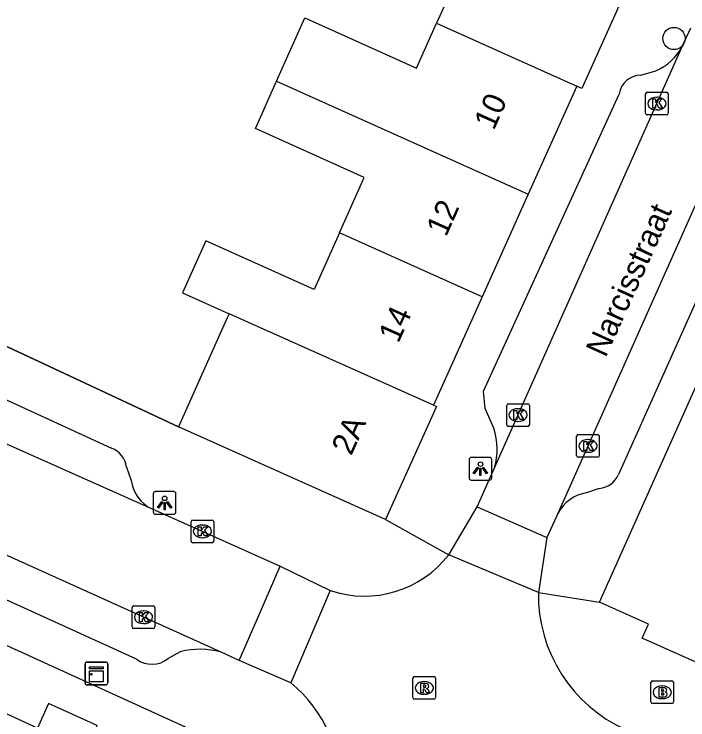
# Model space of a CAD drawing. Extents: x 161845 to 162341, y 381620 to 382158.
# Drawn here: x 162150.69 to 162180.36, y 381756.3 to 381787.37 of the extents above; entities that cross this region are included whole.
import ezdxf

# ---------------------------------------------------------------- set-up
doc = ezdxf.new("R2010")
doc.units = 0
for name, color, linetype in [('IMGEO_Boom', 7, 'Continuous'), ('IMGEO_Brandkraan', 7, 'Continuous'), ('IMGEO_Kast', 7, 'Continuous'), ('IMGEO_Kolk', 7, 'Continuous'), ('IMGEO_Lichtpunt', 7, 'Continuous'), ('IMGEO_Muur', 7, 'Continuous'), ('IMGEO_Openbare_ruimte_label', 7, 'Continuous'), ('IMGEO_Pand', 7, 'Continuous'), ('IMGEO_Pand_nummerreeks', 7, 'Continuous'), ('IMGEO_Rijbaan_lokaal_open', 7, 'Continuous'), ('IMGEO_Rioolput', 7, 'Continuous'), ('IMGEO_Voetpad_open', 7, 'Continuous')]:
    doc.layers.add(name, color=color, linetype=linetype)

msp = doc.modelspace()

# ---------------------------------------------------------------- linework, layer by layer
at = {"layer": 'IMGEO_Boom'}
msp.add_circle((162179.746, 381786.3), 0.489, dxfattribs=at)
at = {"layer": 'IMGEO_Brandkraan'}
for p, q in [((162178.728, 381757.091), (162178.728, 381757.943)), ((162178.803, 381758.017), (162179.655, 381758.017)), ((162179.216, 381757.797), (162179.241, 381757.797)), ((162179.729, 381757.943), (162179.729, 381757.091)), ((162179.239, 381757.237), (162179.214, 381757.237)), ((162179.655, 381757.017), (162178.803, 381757.017))]:
    msp.add_line(p, q, dxfattribs=at)
for points in [[(162178.728, 381757.091), (162178.728, 381757.943)], [(162178.803, 381758.017), (162179.655, 381758.017)], [(162179.729, 381757.943), (162179.729, 381757.091)], [(162179.076, 381757.717), (162179.076, 381757.317), (162179.289, 381757.317)], [(162179.307, 381757.717), (162179.076, 381757.717)], [(162179.255, 381757.636), (162179.201, 381757.636), (162179.201, 381757.56)], [(162179.201, 381757.56), (162179.254, 381757.56)], [(162179.263, 381757.484), (162179.201, 381757.484), (162179.201, 381757.403)], [(162179.201, 381757.403), (162179.263, 381757.403)], [(162179.655, 381757.017), (162178.803, 381757.017)]]:
    msp.add_lwpolyline(points, dxfattribs=at)
for centre, radius, start, end in [((162178.805, 381757.941), 0.0765, 91.552, 178.448), ((162178.805, 381757.941), 0.0765, 91.552, 178.448), ((162179.653, 381757.941), 0.0765, 1.552, 88.448), ((162179.653, 381757.941), 0.0765, 1.552, 88.448), ((162179.256, 381757.598), 0.0379, 267.8285, 90.9355), ((162179.264, 381757.443), 0.0404, 269.8759, 90.5077), ((162179.311, 381757.572), 0.145, 59.4692, 91.5367), ((162179.336, 381757.619), 0.0922, 285.5137, 58.1501), ((162179.341, 381757.427), 0.105, 301.3115, 78.989), ((162179.295, 381757.568), 0.251, 268.6676, 293.5347), ((162178.805, 381757.093), 0.0765, 181.552, 268.448), ((162178.805, 381757.093), 0.0765, 181.552, 268.448), ((162179.653, 381757.093), 0.0765, 271.552, 358.448), ((162179.653, 381757.093), 0.0765, 271.552, 358.448)]:
    msp.add_arc(centre, radius, start, end, dxfattribs=at)
for centre, major_axis, ratio, start_param, end_param in [((162179.215, 381757.517), (-0.387, 0.002), 0.722429, 4.712389, 7.853982), ((162179.24, 381757.517), (-0.39, 0.002), 0.717154, 1.570796, 4.712389)]:
    msp.add_ellipse(centre, major_axis=major_axis, ratio=ratio, start_param=start_param, end_param=end_param, dxfattribs=at)
at = {"layer": 'IMGEO_Kast'}
for p, q in [((162153.808, 381757.922), (162153.808, 381758.763)), ((162153.808, 381758.763), (162153.808, 381757.922)), ((162153.883, 381758.847), (162154.724, 381758.847)), ((162154.724, 381758.847), (162153.883, 381758.847)), ((162154.808, 381758.772), (162154.808, 381757.931)), ((162154.808, 381757.931), (162154.808, 381758.772)), ((162154.733, 381757.847), (162153.892, 381757.847)), ((162153.892, 381757.847), (162154.733, 381757.847))]:
    msp.add_line(p, q, dxfattribs=at)
for points in [[(162154.003, 381758.637), (162154.603, 381758.637), (162154.603, 381758.552), (162154.003, 381758.552), (162154.003, 381758.637)], [(162154.003, 381758.462), (162154.603, 381758.462), (162154.603, 381757.973), (162154.003, 381757.973), (162154.003, 381758.462)]]:
    msp.add_lwpolyline(points, dxfattribs=at)
msp.add_circle((162154.087, 381758.311), 0.0377, dxfattribs=at)
for centre, start, end in [((162153.886, 381758.769), 92.4484, 184.2845), ((162153.886, 381758.769), 92.4484, 184.2845), ((162154.73, 381758.769), 2.4484, 94.2845), ((162154.73, 381758.769), 2.4484, 94.2845), ((162153.886, 381757.925), 182.4484, 274.2845), ((162153.886, 381757.925), 182.4484, 274.2845), ((162154.73, 381757.925), 272.4484, 4.2845), ((162154.73, 381757.925), 272.4484, 4.2845)]:
    msp.add_arc(centre, 0.0779, start, end, dxfattribs=at)
at = {"layer": 'IMGEO_Kolk'}
for p, q in [((162178.569, 381783.937), (162179.421, 381783.937)), ((162178.494, 381783.011), (162178.494, 381783.863)), ((162178.982, 381783.717), (162179.007, 381783.717)), ((162179.495, 381783.863), (162179.495, 381783.011)), ((162179.005, 381783.157), (162178.98, 381783.157)), ((162179.421, 381782.937), (162178.569, 381782.937)), ((162172.455, 381770.222), (162173.307, 381770.222)), ((162172.38, 381769.296), (162172.38, 381770.148)), ((162172.868, 381770.002), (162172.893, 381770.002)), ((162173.381, 381770.148), (162173.381, 381769.296)), ((162172.891, 381769.442), (162172.866, 381769.442)), ((162173.307, 381769.222), (162172.455, 381769.222)), ((162175.458, 381767.939), (162175.458, 381768.791)), ((162175.533, 381768.865), (162176.385, 381768.865)), ((162176.459, 381768.791), (162176.459, 381767.939)), ((162175.946, 381768.645), (162175.971, 381768.645)), ((162175.969, 381768.085), (162175.944, 381768.085)), ((162176.385, 381767.865), (162175.533, 381767.865)), ((162158.478, 381764.174), (162158.478, 381765.026)), ((162158.553, 381765.1), (162159.405, 381765.1)), ((162159.479, 381765.026), (162159.479, 381764.174)), ((162158.966, 381764.88), (162158.991, 381764.88)), ((162158.989, 381764.32), (162158.964, 381764.32)), ((162159.405, 381764.1), (162158.553, 381764.1)), ((162155.884, 381760.397), (162155.884, 381761.249)), ((162155.959, 381761.323), (162156.811, 381761.323)), ((162156.885, 381761.249), (162156.885, 381760.397)), ((162156.372, 381761.103), (162156.397, 381761.103)), ((162156.811, 381760.323), (162155.959, 381760.323)), ((162156.395, 381760.543), (162156.37, 381760.543))]:
    msp.add_line(p, q, dxfattribs=at)
for points in [[(162178.569, 381783.937), (162179.421, 381783.937)], [(162178.494, 381783.011), (162178.494, 381783.863)], [(162178.815, 381783.637), (162178.938, 381783.637), (162178.938, 381783.486), (162179.068, 381783.637), (162179.232, 381783.637), (162179.086, 381783.486), (162179.239, 381783.237), (162179.087, 381783.237), (162179.002, 381783.401), (162178.938, 381783.334), (162178.938, 381783.237), (162178.815, 381783.237), (162178.815, 381783.637)], [(162179.495, 381783.863), (162179.495, 381783.011)], [(162179.421, 381782.937), (162178.569, 381782.937)], [(162172.455, 381770.222), (162173.307, 381770.222)], [(162172.38, 381769.296), (162172.38, 381770.148)], [(162172.701, 381769.922), (162172.824, 381769.922), (162172.824, 381769.771), (162172.954, 381769.922), (162173.118, 381769.922), (162172.972, 381769.771), (162173.125, 381769.522), (162172.973, 381769.522), (162172.888, 381769.686), (162172.824, 381769.619), (162172.824, 381769.522), (162172.701, 381769.522), (162172.701, 381769.922)], [(162173.381, 381770.148), (162173.381, 381769.296)], [(162173.307, 381769.222), (162172.455, 381769.222)], [(162175.458, 381767.939), (162175.458, 381768.791)], [(162175.533, 381768.865), (162176.385, 381768.865)], [(162176.459, 381768.791), (162176.459, 381767.939)], [(162175.779, 381768.565), (162175.902, 381768.565), (162175.902, 381768.414), (162176.032, 381768.565), (162176.196, 381768.565), (162176.05, 381768.414), (162176.203, 381768.165), (162176.051, 381768.165), (162175.966, 381768.329), (162175.902, 381768.262), (162175.902, 381768.165), (162175.779, 381768.165), (162175.779, 381768.565)], [(162176.385, 381767.865), (162175.533, 381767.865)], [(162158.478, 381764.174), (162158.478, 381765.026)], [(162158.553, 381765.1), (162159.405, 381765.1)], [(162159.479, 381765.026), (162159.479, 381764.174)], [(162158.799, 381764.8), (162158.922, 381764.8), (162158.922, 381764.649), (162159.052, 381764.8), (162159.216, 381764.8), (162159.07, 381764.649), (162159.223, 381764.4), (162159.071, 381764.4), (162158.986, 381764.564), (162158.922, 381764.497), (162158.922, 381764.4), (162158.799, 381764.4), (162158.799, 381764.8)], [(162159.405, 381764.1), (162158.553, 381764.1)], [(162155.884, 381760.397), (162155.884, 381761.249)], [(162155.959, 381761.323), (162156.811, 381761.323)], [(162156.885, 381761.249), (162156.885, 381760.397)], [(162156.205, 381761.023), (162156.328, 381761.023), (162156.328, 381760.872), (162156.458, 381761.023), (162156.622, 381761.023), (162156.476, 381760.872), (162156.629, 381760.623), (162156.477, 381760.623), (162156.392, 381760.787), (162156.328, 381760.72), (162156.328, 381760.623), (162156.205, 381760.623), (162156.205, 381761.023)], [(162156.811, 381760.323), (162155.959, 381760.323)]]:
    msp.add_lwpolyline(points, dxfattribs=at)
for centre, start, end in [((162178.571, 381783.861), 91.552, 178.448), ((162178.571, 381783.861), 91.552, 178.448), ((162179.419, 381783.861), 1.552, 88.448), ((162179.419, 381783.861), 1.552, 88.448), ((162178.571, 381783.013), 181.552, 268.448), ((162178.571, 381783.013), 181.552, 268.448), ((162179.419, 381783.013), 271.552, 358.448), ((162179.419, 381783.013), 271.552, 358.448), ((162172.457, 381770.146), 91.552, 178.448), ((162172.457, 381770.146), 91.552, 178.448), ((162173.305, 381770.146), 1.552, 88.448), ((162173.305, 381770.146), 1.552, 88.448), ((162172.457, 381769.298), 181.552, 268.448), ((162172.457, 381769.298), 181.552, 268.448), ((162173.305, 381769.298), 271.552, 358.448), ((162173.305, 381769.298), 271.552, 358.448), ((162175.535, 381768.789), 91.552, 178.448), ((162175.535, 381768.789), 91.552, 178.448), ((162176.383, 381768.789), 1.552, 88.448), ((162176.383, 381768.789), 1.552, 88.448), ((162175.535, 381767.941), 181.552, 268.448), ((162175.535, 381767.941), 181.552, 268.448), ((162176.383, 381767.941), 271.552, 358.448), ((162176.383, 381767.941), 271.552, 358.448), ((162158.555, 381765.024), 91.552, 178.448), ((162158.555, 381765.024), 91.552, 178.448), ((162159.403, 381765.024), 1.552, 88.448), ((162159.403, 381765.024), 1.552, 88.448), ((162158.555, 381764.176), 181.552, 268.448), ((162158.555, 381764.176), 181.552, 268.448), ((162159.403, 381764.176), 271.552, 358.448), ((162159.403, 381764.176), 271.552, 358.448), ((162155.961, 381761.247), 91.552, 178.448), ((162155.961, 381761.247), 91.552, 178.448), ((162156.809, 381761.247), 1.552, 88.448), ((162156.809, 381761.247), 1.552, 88.448), ((162155.961, 381760.399), 181.552, 268.448), ((162155.961, 381760.399), 181.552, 268.448), ((162156.809, 381760.399), 271.552, 358.448), ((162156.809, 381760.399), 271.552, 358.448)]:
    msp.add_arc(centre, 0.0765, start, end, dxfattribs=at)
for centre, major_axis, ratio, start_param, end_param in [((162178.981, 381783.437), (-0.387, 0.002), 0.722429, 4.712389, 7.853982), ((162179.006, 381783.437), (-0.39, 0.002), 0.717154, 1.570796, 4.712389), ((162172.867, 381769.722), (-0.387, 0.002), 0.722429, 4.712389, 7.853982), ((162172.892, 381769.722), (-0.39, 0.002), 0.717154, 1.570796, 4.712389), ((162175.945, 381768.365), (-0.387, 0.002), 0.722429, 4.712389, 7.853982), ((162175.97, 381768.365), (-0.39, 0.002), 0.717154, 1.570796, 4.712389), ((162158.965, 381764.6), (-0.387, 0.002), 0.722429, 4.712389, 7.853982), ((162158.99, 381764.6), (-0.39, 0.002), 0.717154, 1.570796, 4.712389), ((162156.371, 381760.823), (-0.387, 0.002), 0.722429, 4.712389, 7.853982), ((162156.396, 381760.823), (-0.39, 0.002), 0.717154, 1.570796, 4.712389)]:
    msp.add_ellipse(centre, major_axis=major_axis, ratio=ratio, start_param=start_param, end_param=end_param, dxfattribs=at)
at = {"layer": 'IMGEO_Lichtpunt'}
for p, q in [((162170.723, 381767.762), (162170.723, 381766.955)), ((162170.723, 381767.762), (162170.723, 381766.955)), ((162171.625, 381767.857), (162170.817, 381767.857)), ((162171.625, 381767.857), (162170.817, 381767.857)), ((162171.719, 381766.955), (162171.719, 381767.762)), ((162171.719, 381766.955), (162171.719, 381767.762)), ((162170.817, 381766.861), (162171.625, 381766.861)), ((162170.817, 381766.861), (162171.625, 381766.861)), ((162156.817, 381766.255), (162156.817, 381765.448)), ((162156.817, 381766.255), (162156.817, 381765.448)), ((162157.719, 381766.35), (162156.911, 381766.35)), ((162157.719, 381766.35), (162156.911, 381766.35)), ((162157.813, 381765.448), (162157.813, 381766.255)), ((162157.813, 381765.448), (162157.813, 381766.255)), ((162156.911, 381765.354), (162157.719, 381765.354)), ((162156.911, 381765.354), (162157.719, 381765.354))]:
    msp.add_line(p, q, dxfattribs=at)
for points in [[(162171.097, 381767.426), (162171.136, 381767.398), (162170.948, 381767.136), (162170.91, 381767.163), (162171.097, 381767.426)], [(162171.309, 381767.398), (162171.347, 381767.425), (162171.534, 381767.163), (162171.495, 381767.135), (162171.309, 381767.398)], [(162171.199, 381767.378), (162171.246, 381767.378), (162171.246, 381767.056), (162171.199, 381767.056), (162171.199, 381767.378)], [(162157.191, 381765.919), (162157.23, 381765.891), (162157.042, 381765.629), (162157.004, 381765.656), (162157.191, 381765.919)], [(162157.293, 381765.871), (162157.34, 381765.871), (162157.34, 381765.549), (162157.293, 381765.549), (162157.293, 381765.871)], [(162157.403, 381765.891), (162157.441, 381765.918), (162157.628, 381765.656), (162157.589, 381765.628), (162157.403, 381765.891)]]:
    msp.add_lwpolyline(points, dxfattribs=at)
for centre in [(162171.222, 381767.56), (162157.316, 381766.053)]:
    msp.add_circle(centre, 0.0994, dxfattribs=at)
for centre, start, end in [((162170.817, 381767.762), 90, 180), ((162170.817, 381767.762), 90, 180), ((162171.625, 381767.762), 0, 90), ((162171.625, 381767.762), 0, 90), ((162170.817, 381766.955), 180, 270), ((162170.817, 381766.955), 180, 270), ((162171.625, 381766.955), 270, 0), ((162171.625, 381766.955), 270, 360), ((162156.911, 381766.255), 90, 180), ((162156.911, 381766.255), 90, 180), ((162157.719, 381766.255), 0, 90), ((162157.719, 381766.255), 0, 90), ((162156.911, 381765.448), 180, 270), ((162156.911, 381765.448), 180, 270), ((162157.719, 381765.448), 270, 0), ((162157.719, 381765.448), 270, 360)]:
    msp.add_arc(centre, 0.0946, start, end, dxfattribs=at)
at = {"layer": 'IMGEO_Muur'}
msp.add_lwpolyline([(162143.794, 381775.807), (162157.924, 381769.21)], dxfattribs=at)
at = {"layer": 'IMGEO_Pand'}
for points in [[(162166.688, 381794.129), (162165.607, 381791.72), (162170.45, 381789.548), (162169.293, 381786.97)], [(162177.973, 381789.202), (162175.685, 381784.102), (162175.462, 381784.202)], [(162162.243, 381784.418), (162163.493, 381787.205), (162168.409, 381785), (162169.293, 381786.97)], [(162169.293, 381786.97), (162175.462, 381784.202)], [(162165.013, 381777.742), (162166.109, 381780.186), (162161.31, 381782.339), (162162.243, 381784.418)], [(162162.243, 381784.418), (162173.327, 381779.442)], [(162175.462, 381784.202), (162173.327, 381779.442)], [(162173.327, 381779.442), (162171.298, 381774.92)], [(162165.013, 381777.742), (162163.894, 381775.248), (162159.127, 381777.386), (162158.1, 381775.099), (162160.153, 381774.18)], [(162171.298, 381774.92), (162165.013, 381777.742)], [(162171.298, 381774.92), (162169.159, 381770.151)], [(162160.153, 381774.18), (162160.073, 381774.001), (162159.692, 381773.153), (162157.924, 381769.21)], [(162169.159, 381770.151), (162160.153, 381774.18)], [(162176.463, 381761.49), (162181.231, 381772.154)], [(162169.159, 381770.151), (162169.281, 381770.095), (162167.048, 381765.117)], [(162167.048, 381765.117), (162157.924, 381769.21)], [(162182.722, 381757.941), (162178.347, 381759.906), (162178.623, 381760.52), (162176.463, 381761.49)], [(162152.399, 381751.795), (162154.341, 381756.054), (162152.205, 381757.027), (162151.711, 381755.944), (162149.035, 381757.163), (162150.175, 381759.665)], [(162150.175, 381759.665), (162159.059, 381755.615), (162160.739, 381754.849)]]:
    msp.add_lwpolyline(points, dxfattribs=at)
at = {"layer": 'IMGEO_Rijbaan_lokaal_open'}
for points in [[(162180.125, 381785.972), (162180.483, 381786.774)], [(162171.847, 381767.4), (162180.125, 381785.972)], [(162180.682, 381778.946), (162174.63, 381765.392)], [(162142.624, 381771.89), (162156.759, 381765.589)], [(162159.801, 381759.281), (162140.84, 381767.845)], [(162171.08, 381765.679), (162171.847, 381767.4)], [(162156.759, 381765.589), (162162.401, 381763.074)], [(162169.828, 381763.573), (162171.08, 381765.679)], [(162171.08, 381765.679), (162172.543, 381765.035), (162174.154, 381764.325)], [(162174.63, 381765.392), (162174.568, 381765.252), (162174.154, 381764.325)], [(162174.154, 381764.325), (162173.775, 381761.912)], [(162173.775, 381761.912), (162169.828, 381763.573)], [(162160.604, 381758.918), (162161.503, 381760.997), (162162.401, 381763.074)], [(162162.401, 381763.074), (162164.609, 381762)], [(162164.609, 381762), (162162.872, 381757.937)], [(162160.604, 381758.918), (162159.801, 381759.281)], [(162162.872, 381757.937), (162160.604, 381758.918)]]:
    msp.add_lwpolyline(points, dxfattribs=at)
for centre, radius, start, end in [((162166.119, 381766.433), 4.683, 251.1846, 322.3609), ((162180.269, 381761.808), 6.495, 179.0828, 245.8423), ((162158.757, 381753.042), 6.395, 359.0955, 49.9461)]:
    msp.add_arc(centre, radius, start, end, dxfattribs=at)
at = {"layer": 'IMGEO_Rioolput'}
for p, q in [((162168.249, 381757.282), (162168.249, 381758.134)), ((162168.324, 381758.208), (162169.176, 381758.208)), ((162169.25, 381758.134), (162169.25, 381757.282)), ((162168.737, 381757.988), (162168.762, 381757.988)), ((162169.176, 381757.208), (162168.324, 381757.208)), ((162168.76, 381757.428), (162168.735, 381757.428))]:
    msp.add_line(p, q, dxfattribs=at)
for points in [[(162168.249, 381757.282), (162168.249, 381758.134)], [(162168.324, 381758.208), (162169.176, 381758.208)], [(162169.25, 381758.134), (162169.25, 381757.282)], [(162168.838, 381757.906), (162168.586, 381757.908), (162168.586, 381757.508)], [(162168.764, 381757.827), (162168.71, 381757.827), (162168.71, 381757.746)], [(162168.586, 381757.508), (162168.71, 381757.508), (162168.71, 381757.67), (162168.721, 381757.67)], [(162168.71, 381757.746), (162168.762, 381757.746)], [(162168.768, 381757.641), (162168.839, 381757.508), (162168.979, 381757.508), (162168.914, 381757.634)], [(162169.176, 381757.208), (162168.324, 381757.208)]]:
    msp.add_lwpolyline(points, dxfattribs=at)
for centre, radius, start, end in [((162168.326, 381758.132), 0.0765, 91.552, 178.448), ((162168.326, 381758.132), 0.0765, 91.552, 178.448), ((162169.174, 381758.132), 0.0765, 1.552, 88.448), ((162169.174, 381758.132), 0.0765, 1.552, 88.448), ((162168.77, 381757.731), 0.0964, 77.0061, 93.1865), ((162168.784, 381757.788), 0.0378, 276.6634, 79.6772), ((162168.837, 381757.796), 0.109, 350.3612, 89.416), ((162168.835, 381757.796), 0.112, 277.5842, 350.9817), ((162168.72, 381757.617), 0.0533, 26.0293, 88.6989), ((162168.746, 381757.935), 0.19, 274.7715, 282.9687), ((162168.819, 381757.581), 0.108, 29.5134, 73.7905), ((162168.326, 381757.284), 0.0765, 181.552, 268.448), ((162168.326, 381757.284), 0.0765, 181.552, 268.448), ((162169.174, 381757.284), 0.0765, 271.552, 358.448), ((162169.174, 381757.284), 0.0765, 271.552, 358.448)]:
    msp.add_arc(centre, radius, start, end, dxfattribs=at)
for centre, major_axis, ratio, start_param, end_param in [((162168.736, 381757.708), (-0.387, 0.002), 0.722429, 4.712389, 7.853982), ((162168.761, 381757.708), (-0.39, 0.002), 0.717154, 1.570796, 4.712389)]:
    msp.add_ellipse(centre, major_axis=major_axis, ratio=ratio, start_param=start_param, end_param=end_param, dxfattribs=at)
at = {"layer": 'IMGEO_Voetpad_open'}
for points in [[(162178.284, 381784.679), (162178.944, 381784.872)], [(162171.813, 381769.138), (162171.429, 381770.013), (162171.362, 381770.774), (162177.336, 381783.85)], [(162157.924, 381769.21), (162143.794, 381775.807)], [(162181.09, 381775.564), (162177.306, 381767.105)], [(162146.158, 381772.316), (162154.972, 381768.266)], [(162155.636, 381767.431), (162155.842, 381766.848)], [(162176.458, 381766.493), (162175.9, 381766.3)], [(162156.078, 381758.979), (162142.584, 381765.103)], [(162167.048, 381765.117), (162169.828, 381763.573)], [(162173.775, 381761.912), (162176.463, 381761.49)], [(162158.006, 381759.304), (162157.474, 381759.01)]]:
    msp.add_lwpolyline(points, dxfattribs=at)
for centre, radius, start, end in [((162177.907, 381787.169), 2.521, 294.2948, 331.6377), ((162178.271, 381783.737), 0.942, 89.2344, 173.1032), ((162168.944, 381768.213), 3.014, 344.3611, 17.8803), ((162154.623, 381767.307), 1.02, 6.9692, 70.0149), ((162176.35, 381767.536), 1.049, 275.9182, 335.7176), ((162157.462, 381767.064), 1.634, 187.605, 244.5309), ((162176.165, 381764.586), 1.734, 98.8075, 152.319), ((162158.86, 381755.894), 3.516, 74.474, 104.0578), ((162156.756, 381759.878), 1.126, 232.9567, 309.5875)]:
    msp.add_arc(centre, radius, start, end, dxfattribs=at)

# ---------------------------------------------------------------- texts
at = {"layer": 'IMGEO_Openbare_ruimte_label'}
msp.add_text('Narcisstraat', height=1, rotation=65.6651, dxfattribs=at).set_placement((162176.738, 381772.218))
at = {"layer": 'IMGEO_Pand_nummerreeks'}
for s, rotation, p in [('10', 65.8396, (162171.812, 381782.223)), ('12', 65.8396, (162169.709, 381777.533)), ('14', 65.8386, (162167.608, 381772.851)), ('2A', 65.8386, (162165.536, 381767.903))]:
    msp.add_text(s, height=1, rotation=rotation, dxfattribs=at).set_placement(p)

doc.saveas('drawing.dxf')
